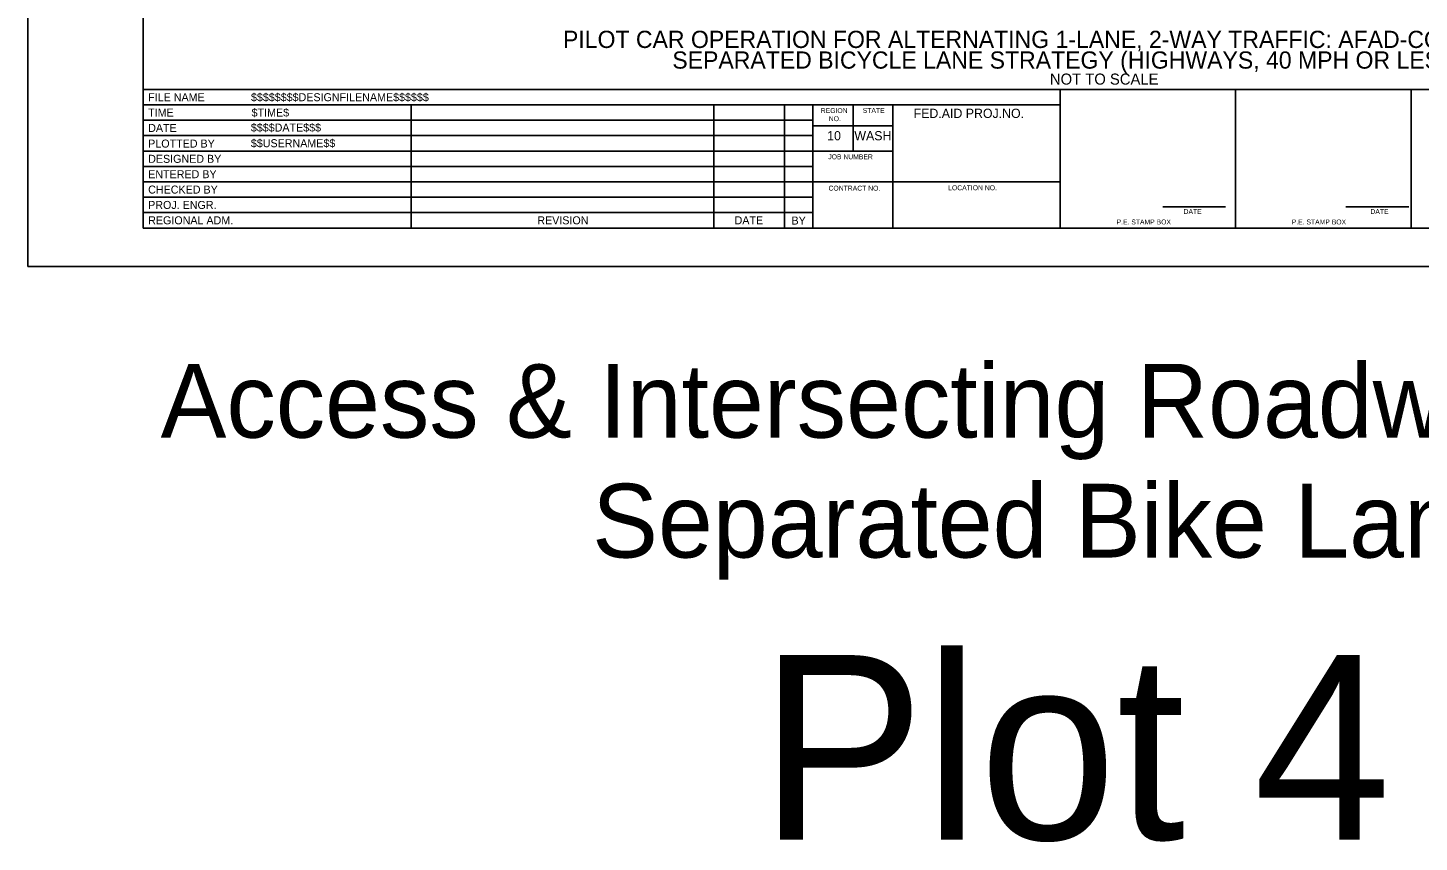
# Model space of a CAD drawing. Extents: x 99999.1 to 100095.7, y 99995 to 100010.7.
# Drawn here: x 100059.06 to 100070.38, y 99995.01 to 100001.63 of the extents above; entities that cross this region are included whole.
import ezdxf

# ---------------------------------------------------------------- set-up
doc = ezdxf.new("R2010")
doc.units = 0
for name, color, linetype in [('SH_DE_DetailHeading1Text', 7, 'Continuous'), ('SH_GI_PlotLimits', 7, 'Continuous'), ('SH_GI_SheetBorder', 7, 'Continuous'), ('SH_GI_SheetLocationText', 7, 'Continuous'), ('SH_GI_SheetTextInCells', 7, 'Continuous'), ('SH_GI_TitleBlockText', 7, 'Continuous')]:
    doc.layers.add(name, color=color, linetype=linetype)

msp = doc.modelspace()

# ---------------------------------------------------------------- linework, layer by layer
at = {"layer": 'SH_GI_PlotLimits'}
msp.add_lwpolyline([(100059.062, 99999.687), (100076.062, 99999.687), (100076.062, 100010.687), (100059.062, 100010.687)], close=True, dxfattribs=at)
at = {"layer": 'SH_GI_SheetBorder'}
for p, q in [((100060, 100010.375), (100060, 100000)), ((100060, 100001.126), (100075.75, 100001.126)), ((100067.457, 100000), (100067.457, 100001.126)), ((100068.883, 100000), (100068.883, 100001.126)), ((100070.309, 100001.126), (100070.309, 100000)), ((100060, 100001.001), (100067.457, 100001.001)), ((100062.179, 100001.001), (100062.179, 100000)), ((100064.641, 100001.001), (100064.641, 100000)), ((100065.216, 100001.001), (100065.216, 100000)), ((100065.445, 100001.001), (100065.445, 100000)), ((100065.772, 100000.625), (100065.772, 100001.001)), ((100066.096, 100000), (100066.096, 100001.001)), ((100060, 100000.876), (100062.182, 100000.876)), ((100062.182, 100000.876), (100065.447, 100000.876)), ((100066.096, 100000.831), (100065.447, 100000.831)), ((100060, 100000.751), (100062.182, 100000.751)), ((100062.182, 100000.751), (100065.447, 100000.751)), ((100060, 100000.625), (100065.447, 100000.625)), ((100066.096, 100000.625), (100065.447, 100000.625)), ((100060, 100000.5), (100065.447, 100000.5)), ((100060, 100000.375), (100065.447, 100000.375)), ((100067.457, 100000.375), (100065.447, 100000.375)), ((100060, 100000.25), (100065.447, 100000.25)), ((100060, 100000.125), (100065.447, 100000.125)), ((100068.29, 100000.173), (100068.802, 100000.173)), ((100069.78, 100000.173), (100070.291, 100000.173)), ((100060, 100000), (100075.75, 100000))]:
    msp.add_line(p, q, dxfattribs=at)

# ---------------------------------------------------------------- texts
at = {"layer": 'SH_DE_DetailHeading1Text'}
for s, height, p in [('PILOT CAR OPERATION FOR ALTERNATING 1-LANE, 2-WAY TRAFFIC: AFAD-CONTROLLED', 0.14, (100063.414, 100001.464)), ('SEPARATED BICYCLE LANE STRATEGY (HIGHWAYS, 40 MPH OR LESS)', 0.14, (100064.303, 100001.296)), ('NOT TO SCALE', 0.09, (100067.373, 100001.166))]:
    msp.add_text(s, height=height, rotation=360, dxfattribs=at).set_placement(p)
at = {"layer": 'SH_GI_SheetLocationText'}
for s, height, p in [('Access & Intersecting Roadway Details', 0.6, (100060.142, 99998.295)), ('Separated Bike Lane', 0.6, (100063.651, 99997.32)), ('Plot 4', 1.5, (100065.015, 99995.027))]:
    msp.add_text(s, height=height, dxfattribs=at).set_placement(p)
at = {"layer": 'SH_GI_SheetTextInCells'}
for s, height, p in [('FILE NAME', 0.0651, (100060.041, 100001.031)), ('TIME', 0.0651, (100060.041, 100000.906)), ('REGION', 0.04, (100065.51, 100000.935)), ('NO.', 0.04, (100065.575, 100000.869)), ('STATE', 0.04, (100065.851, 100000.936)), ('FED.AID PROJ.NO.', 0.07506, (100066.265, 100000.895)), ('DATE', 0.0651, (100060.041, 100000.781)), ('10', 0.0751, (100065.562, 100000.713)), ('WASH', 0.0751, (100065.783, 100000.713)), ('PLOTTED BY', 0.0651, (100060.041, 100000.654)), ('DESIGNED BY', 0.06505, (100060.041, 100000.53)), ('JOB NUMBER', 0.04, (100065.571, 100000.559)), ('ENTERED BY', 0.0651, (100060.041, 100000.405)), ('CHECKED BY', 0.0651, (100060.041, 100000.28)), ('CONTRACT NO.', 0.04003, (100065.573, 100000.304)), ('LOCATION NO.', 0.04003, (100066.546, 100000.307)), ('PROJ. ENGR.', 0.06505, (100060.041, 100000.155)), ('REGIONAL ADM.', 0.06505, (100060.041, 100000.03)), ('REVISION', 0.0651, (100063.205, 100000.03)), ('DATE', 0.04, (100068.46, 100000.114)), ('DATE', 0.04, (100069.979, 100000.114)), ('DATE', 0.0651, (100064.809, 100000.03)), ('BY', 0.0651, (100065.272, 100000.028)), ('P.E. STAMP BOX', 0.04003, (100067.915, 100000.029)), ('P.E. STAMP BOX', 0.04003, (100069.339, 100000.029))]:
    msp.add_text(s, height=height, dxfattribs=at).set_placement(p)
at = {"layer": 'SH_GI_TitleBlockText'}
for s, height, p in [('$$$$$$$$DESIGNFILENAME$$$$$$', 0.06505, (100060.877, 100001.031)), ('$TIME$', 0.0651, (100060.882, 100000.906)), ('$$$$DATE$$$', 0.06505, (100060.876, 100000.784)), ('$$USERNAME$$', 0.06505, (100060.876, 100000.657))]:
    msp.add_text(s, height=height, dxfattribs=at).set_placement(p)

doc.saveas('drawing.dxf')
